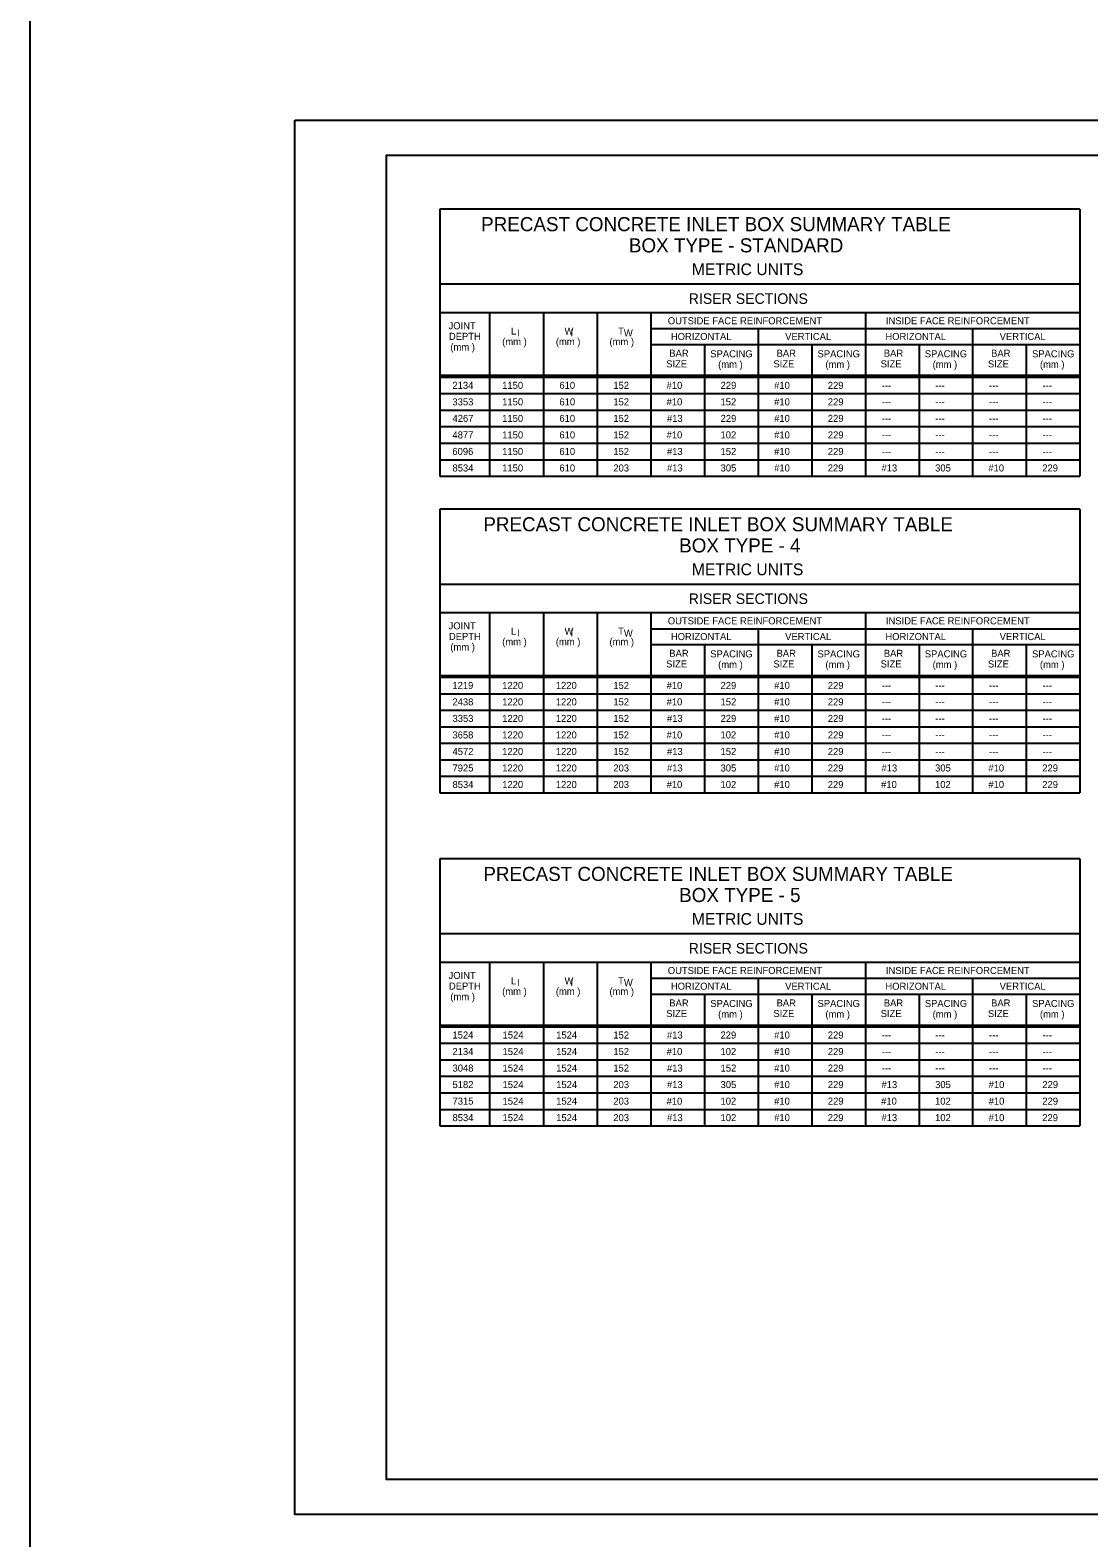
# Model space of a CAD drawing. Extents: x -6420 to 49575, y -4552 to 11624.
# Drawn here: x 34295 to 35776, y -102 to 2006 of the extents above; entities that cross this region are included whole.
import ezdxf

# ---------------------------------------------------------------- set-up
doc = ezdxf.new("R2010")
doc.units = 0
doc.layers.add('1', color=7, linetype='Continuous')
doc.layers.add('4', color=7, linetype='Continuous')

msp = doc.modelspace()

# ---------------------------------------------------------------- linework, layer by layer
at = {"layer": '1'}
for p, q in [((34868.5, 1755.6), (34868.5, 1382.3)), ((35763.5, 1755.6), (34868.5, 1755.6)), ((35763.5, 1755.6), (35763.5, 1382.3)), ((35763.5, 1650.6), (34868.5, 1650.6)), ((35763.5, 1610.6), (34868.5, 1610.6)), ((34938.5, 1382.3), (34938.5, 1610.6)), ((35013.5, 1610.6), (35013.5, 1382.3)), ((35088.5, 1610.6), (35088.5, 1382.3)), ((35163.5, 1610.6), (35163.5, 1382.3)), ((35463.5, 1610.6), (35463.5, 1382.3)), ((35163.5, 1588.6), (35463.5, 1588.6)), ((35313.5, 1588.6), (35313.5, 1382.3)), ((35463.5, 1588.6), (35763.5, 1588.6)), ((35613.5, 1588.6), (35613.5, 1382.3)), ((35163.5, 1566.6), (35463.5, 1566.6)), ((35238.5, 1566.6), (35238.5, 1382.3)), ((35388.5, 1566.6), (35388.5, 1382.3)), ((35463.5, 1566.6), (35763.5, 1566.6)), ((35538.5, 1566.6), (35538.5, 1382.3)), ((35688.5, 1566.6), (35688.5, 1382.3)), ((34868.5, 1523.4), (35763.5, 1523.4)), ((34868.5, 1520.9), (35763.5, 1520.9)), ((34868.5, 1497.8), (35763.5, 1497.8)), ((34868.5, 1474.7), (35763.5, 1474.7)), ((34868.5, 1451.6), (35763.5, 1451.6)), ((34868.5, 1428.5), (35763.5, 1428.5)), ((34868.5, 1405.4), (35763.5, 1405.4)), ((34868.5, 1382.3), (35763.5, 1382.3)), ((34868.5, 1336.1), (34868.5, 939.7)), ((35763.5, 1336.1), (34868.5, 1336.1)), ((35763.5, 1336.1), (35763.5, 939.7)), ((35763.5, 1231.1), (34868.5, 1231.1)), ((35763.5, 1191.1), (34868.5, 1191.1)), ((34938.5, 939.7), (34938.5, 1191.1)), ((35013.5, 1191.1), (35013.5, 939.7)), ((35088.5, 1191.1), (35088.5, 939.7)), ((35163.5, 1191.1), (35163.5, 939.7)), ((35463.5, 1191.1), (35463.5, 939.7)), ((35163.5, 1169.1), (35463.5, 1169.1)), ((35313.5, 1169.1), (35313.5, 939.7)), ((35463.5, 1169.1), (35763.5, 1169.1)), ((35613.5, 1169.1), (35613.5, 939.7)), ((35163.5, 1147.1), (35463.5, 1147.1)), ((35238.5, 1147.1), (35238.5, 939.7)), ((35388.5, 1147.1), (35388.5, 939.7)), ((35463.5, 1147.1), (35763.5, 1147.1)), ((35538.5, 1147.1), (35538.5, 939.7)), ((35688.5, 1147.1), (35688.5, 939.7)), ((34868.5, 1103.9), (35763.5, 1103.9)), ((34868.5, 1101.4), (35763.5, 1101.4)), ((34868.5, 1078.3), (35763.5, 1078.3)), ((34868.5, 1055.2), (35763.5, 1055.2)), ((34868.5, 1032.1), (35763.5, 1032.1)), ((34868.5, 1009), (35763.5, 1009)), ((34868.5, 985.9), (35763.5, 985.9)), ((34868.5, 962.8), (35763.5, 962.8)), ((34868.5, 939.7), (35763.5, 939.7)), ((34868.5, 847.3), (34868.5, 474.1)), ((35763.5, 847.3), (34868.5, 847.3)), ((35763.5, 847.3), (35763.5, 474.1)), ((35763.5, 742.4), (34868.5, 742.4)), ((35763.5, 702.4), (34868.5, 702.4)), ((34938.5, 474.1), (34938.5, 702.4)), ((35013.5, 702.4), (35013.5, 474.1)), ((35088.5, 702.4), (35088.5, 474.1)), ((35163.5, 702.4), (35163.5, 474.1)), ((35463.5, 702.4), (35463.5, 474.1)), ((35163.5, 680.4), (35463.5, 680.4)), ((35313.5, 680.4), (35313.5, 474.1)), ((35463.5, 680.4), (35763.5, 680.4)), ((35613.5, 680.4), (35613.5, 474.1)), ((35163.5, 658.4), (35463.5, 658.4)), ((35238.5, 658.4), (35238.5, 474.1)), ((35388.5, 658.4), (35388.5, 474.1)), ((35463.5, 658.4), (35763.5, 658.4)), ((35538.5, 658.4), (35538.5, 474.1)), ((35688.5, 658.4), (35688.5, 474.1)), ((34868.5, 615.1), (35763.5, 615.1)), ((34868.5, 612.7), (35763.5, 612.7)), ((34868.5, 589.5), (35763.5, 589.5)), ((34868.5, 566.5), (35763.5, 566.5)), ((34868.5, 543.4), (35763.5, 543.4)), ((34868.5, 520.3), (35763.5, 520.3)), ((34868.5, 497.2), (35763.5, 497.2)), ((34868.5, 474.1), (35763.5, 474.1))]:
    msp.add_line(p, q, dxfattribs=at)
msp.add_lwpolyline([(34295.4, 6319.6), (48971.6, 6319.6), (48971.6, -4552.2), (34295.4, -4552.2)], close=True, dxfattribs=at)
msp.add_lwpolyline([(37372.3, -19.8), (37372.3, 1830.6), (34793.5, 1830.6), (34793.5, -19.8), (37372.3, -19.8), (37372.3, 66.7), (36716.1, 66.7), (36716.1, 278.9), (37372.3, 278.9), (37372.3, 373.9), (36716.1, 373.9), (36716.1, -19.8), (36974.7, -19.8), (36974.7, 66.7), (36974.7, -19.8), (37227.3, -19.8), (37227.3, 66.7), (37227.3, 26.3), (37372.3, 26.3)], dxfattribs=at)
at = {"layer": '4'}
msp.add_lwpolyline([(34665.6, 1879.8), (37424.8, 1879.8), (37424.8, -69), (34665.6, -69)], close=True, dxfattribs=at)

# ---------------------------------------------------------------- texts
at = {"layer": '1'}
for s, height, p in [('PRECAST CONCRETE INLET BOX SUMMARY TABLE', 19.685, (34926.1, 1724.8)), ('BOX TYPE - STANDARD', 19.685, (35132.8, 1695.2)), ('METRIC UNITS', 16.404, (35220.8, 1663.4)), ('RISER SECTIONS', 14.764, (35216.4, 1623.2)), ('OUTSIDE FACE REINFORCEMENT', 9.843, (35187.2, 1594.7)), ('INSIDE FACE REINFORCEMENT', 9.843, (35492.2, 1594.7)), ('JOINT', 9.84, (34880.6, 1587.7)), ('DEPTH', 9.84, (34881.1, 1572.9)), ('L ', 9.84, (34967.8, 1580.3)), ('I', 9.84, (34976.8, 1577.7)), ('W ', 9.84, (35042.8, 1580.3)), ('I', 9.84, (35051.2, 1577.8)), ('T ', 9.84, (35117.8, 1580.3)), ('W', 9.84, (35125.8, 1577.6)), ('HORIZONTAL', 9.84, (35191.5, 1572.7)), ('VERTICAL', 9.84, (35351.3, 1572.7)), ('HORIZONTAL', 9.84, (35491.5, 1572.7)), ('VERTICAL', 9.84, (35651.3, 1572.7)), ('(mm )', 9.84, (34883.1, 1558)), ('(mm )', 9.84, (34955.6, 1565.5)), ('(mm )', 9.84, (35030.6, 1565.5)), ('(mm )', 9.84, (35105.6, 1565.5)), ('SIZE', 9.84, (35184.9, 1534.4)), ('BAR', 9.84, (35189.3, 1549.3)), ('SPACING', 9.84, (35246.6, 1548.5)), ('(mm )', 9.84, (35257.6, 1533.7)), ('SIZE', 9.84, (35334.9, 1534.4)), ('BAR', 9.84, (35339.3, 1549.3)), ('SPACING', 9.84, (35396.6, 1548.5)), ('(mm )', 9.84, (35407.6, 1533.7)), ('SIZE', 9.84, (35484.9, 1534.4)), ('BAR', 9.84, (35489.3, 1549.3)), ('SPACING', 9.84, (35546.6, 1548.5)), ('(mm )', 9.84, (35557.6, 1533.7)), ('SIZE', 9.84, (35634.9, 1534.4)), ('BAR', 9.84, (35639.3, 1549.3)), ('SPACING', 9.84, (35696.6, 1548.5)), ('(mm )', 9.84, (35707.6, 1533.7)), ('2134', 9.84, (34886, 1504.4)), ('1150', 9.84, (34955.6, 1504.4)), ('610', 9.84, (35035.6, 1504.4)), ('152', 9.84, (35111, 1504.4)), ('#10', 9.84, (35185.5, 1504.4)), ('229', 9.84, (35261, 1504.4)), ('#10', 9.84, (35335.9, 1504.4)), ('229', 9.84, (35411, 1504.4)), ('---', 9.84, (35486.4, 1504.4)), ('---', 9.84, (35561.4, 1504.4)), ('---', 9.84, (35636.4, 1504.4)), ('---', 9.84, (35711.4, 1504.4)), ('3353', 9.84, (34886, 1481.3)), ('1150', 9.84, (34955.6, 1481.3)), ('610', 9.84, (35035.6, 1481.3)), ('152', 9.84, (35111, 1481.3)), ('#10', 9.84, (35185.5, 1481.3)), ('152', 9.84, (35260.9, 1481.3)), ('#10', 9.84, (35335.9, 1481.3)), ('229', 9.84, (35411, 1481.3)), ('---', 9.84, (35486.4, 1481.3)), ('---', 9.84, (35561.4, 1481.3)), ('---', 9.84, (35636.4, 1481.3)), ('---', 9.84, (35711.4, 1481.3)), ('4267', 9.84, (34886.1, 1458.2)), ('1150', 9.84, (34955.6, 1458.2)), ('610', 9.84, (35035.6, 1458.2)), ('152', 9.84, (35111, 1458.2)), ('#13', 9.84, (35186, 1458.2)), ('229', 9.84, (35261, 1458.2)), ('#10', 9.84, (35335.9, 1458.2)), ('229', 9.84, (35411, 1458.2)), ('---', 9.84, (35486.4, 1458.2)), ('---', 9.84, (35561.4, 1458.2)), ('---', 9.84, (35636.4, 1458.2)), ('---', 9.84, (35711.4, 1458.2)), ('4877', 9.84, (34886, 1435.1)), ('1150', 9.84, (34955.6, 1435.1)), ('610', 9.84, (35035.6, 1435.1)), ('152', 9.84, (35111, 1435.1)), ('#10', 9.84, (35185.5, 1435.1)), ('102', 9.84, (35260.9, 1435.1)), ('#10', 9.84, (35335.9, 1435.1)), ('229', 9.84, (35411, 1435.1)), ('---', 9.84, (35486.4, 1435.1)), ('---', 9.84, (35561.4, 1435.1)), ('---', 9.84, (35636.4, 1435.1)), ('---', 9.84, (35711.4, 1435.1)), ('6096', 9.84, (34885.9, 1412)), ('1150', 9.84, (34955.6, 1412)), ('610', 9.84, (35035.6, 1412)), ('152', 9.84, (35111, 1412)), ('#13', 9.84, (35186, 1412)), ('152', 9.84, (35261, 1412)), ('#10', 9.84, (35335.9, 1412)), ('229', 9.84, (35411, 1412)), ('---', 9.84, (35486.4, 1412)), ('---', 9.84, (35561.4, 1412)), ('---', 9.84, (35636.4, 1412)), ('---', 9.84, (35711.4, 1412)), ('8534', 9.84, (34886.1, 1388.9)), ('1150', 9.84, (34955.6, 1388.9)), ('610', 9.84, (35035.6, 1388.9)), ('203', 9.84, (35111, 1388.9)), ('#13', 9.84, (35186, 1388.9)), ('305', 9.84, (35261, 1388.9)), ('#10', 9.84, (35335.9, 1388.9)), ('229', 9.84, (35410.9, 1388.9)), ('#13', 9.84, (35486, 1388.9)), ('305', 9.84, (35561, 1388.9)), ('#10', 9.84, (35635.5, 1388.9)), ('229', 9.84, (35710.9, 1388.9)), ('PRECAST CONCRETE INLET BOX SUMMARY TABLE', 19.685, (34929.2, 1305.3)), ('BOX TYPE - 4', 19.685, (35203.1, 1275.7)), ('METRIC UNITS', 16.404, (35220.8, 1243.9)), ('RISER SECTIONS', 14.764, (35216.4, 1203.7)), ('OUTSIDE FACE REINFORCEMENT', 9.843, (35187.2, 1175.2)), ('INSIDE FACE REINFORCEMENT', 9.843, (35492.2, 1175.2)), ('JOINT', 9.84, (34880.6, 1168.2)), ('DEPTH', 9.84, (34881.1, 1153.4)), ('L ', 9.84, (34967.8, 1160.8)), ('I', 9.84, (34976.8, 1158.3)), ('W ', 9.84, (35042.8, 1160.8)), ('I', 9.84, (35051.2, 1158.3)), ('T ', 9.84, (35117.8, 1160.8)), ('W', 9.84, (35125.8, 1158.1)), ('HORIZONTAL', 9.84, (35191.5, 1153.2)), ('VERTICAL', 9.84, (35351.3, 1153.2)), ('HORIZONTAL', 9.84, (35491.5, 1153.2)), ('VERTICAL', 9.84, (35651.3, 1153.2)), ('(mm )', 9.84, (34883.1, 1138.6)), ('(mm )', 9.84, (34955.6, 1146)), ('(mm )', 9.84, (35030.6, 1146)), ('(mm )', 9.84, (35105.6, 1146)), ('BAR', 9.84, (35189.3, 1129.8)), ('SPACING', 9.84, (35246.6, 1129)), ('BAR', 9.84, (35339.3, 1129.8)), ('SPACING', 9.84, (35396.6, 1129)), ('BAR', 9.84, (35489.3, 1129.8)), ('SPACING', 9.84, (35546.6, 1129)), ('BAR', 9.84, (35639.3, 1129.8)), ('SPACING', 9.84, (35696.6, 1129)), ('SIZE', 9.84, (35184.9, 1114.9)), ('(mm )', 9.84, (35257.6, 1114.2)), ('SIZE', 9.84, (35334.9, 1114.9)), ('(mm )', 9.84, (35407.6, 1114.2)), ('SIZE', 9.84, (35484.9, 1114.9)), ('(mm )', 9.84, (35557.6, 1114.2)), ('SIZE', 9.84, (35634.9, 1114.9)), ('(mm )', 9.84, (35707.6, 1114.2)), ('1219', 9.84, (34885.9, 1084.9)), ('1220', 9.84, (34955.6, 1084.9)), ('1220', 9.84, (35030.6, 1084.9)), ('152', 9.84, (35111, 1084.9)), ('#10', 9.84, (35185.5, 1084.9)), ('229', 9.84, (35261, 1084.9)), ('#10', 9.84, (35335.9, 1085)), ('229', 9.84, (35411, 1084.9)), ('---', 9.84, (35486.4, 1084.9)), ('---', 9.84, (35561.4, 1084.9)), ('---', 9.84, (35636.4, 1084.9)), ('---', 9.84, (35711.4, 1084.9)), ('2438', 9.84, (34886, 1061.9)), ('1220', 9.84, (34955.6, 1061.9)), ('1220', 9.84, (35030.6, 1061.9)), ('152', 9.84, (35111, 1061.9)), ('#10', 9.84, (35185.5, 1061.9)), ('152', 9.84, (35261, 1061.9)), ('#10', 9.84, (35335.9, 1061.9)), ('229', 9.84, (35411, 1061.9)), ('---', 9.84, (35486.4, 1061.9)), ('---', 9.84, (35561.4, 1061.9)), ('---', 9.84, (35636.4, 1061.9)), ('---', 9.84, (35711.4, 1061.9)), ('3353', 9.84, (34886.1, 1038.8)), ('1220', 9.84, (34955.6, 1038.8)), ('1220', 9.84, (35030.6, 1038.8)), ('152', 9.84, (35111, 1038.8)), ('#13', 9.84, (35186, 1038.8)), ('229', 9.84, (35261, 1038.8)), ('#10', 9.84, (35335.9, 1038.8)), ('229', 9.84, (35411, 1038.8)), ('---', 9.84, (35486.4, 1038.8)), ('---', 9.84, (35561.4, 1038.8)), ('---', 9.84, (35636.4, 1038.8)), ('---', 9.84, (35711.4, 1038.8)), ('3658', 9.84, (34886, 1015.7)), ('1220', 9.84, (34955.6, 1015.7)), ('1220', 9.84, (35030.6, 1015.7)), ('152', 9.84, (35111, 1015.7)), ('#10', 9.84, (35185.5, 1015.7)), ('102', 9.84, (35260.9, 1015.7)), ('#10', 9.84, (35335.9, 1015.7)), ('229', 9.84, (35411, 1015.7)), ('---', 9.84, (35486.4, 1015.7)), ('---', 9.84, (35561.4, 1015.7)), ('---', 9.84, (35636.4, 1015.7)), ('---', 9.84, (35711.4, 1015.7)), ('4572', 9.84, (34886.1, 992.6)), ('1220', 9.84, (34955.6, 992.6)), ('1220', 9.84, (35030.6, 992.6)), ('152', 9.84, (35111, 992.6)), ('#13', 9.84, (35186, 992.6)), ('152', 9.84, (35261, 992.6)), ('#10', 9.84, (35335.9, 992.6)), ('229', 9.84, (35411, 992.6)), ('---', 9.84, (35486.4, 992.6)), ('---', 9.84, (35561.4, 992.6)), ('---', 9.84, (35636.4, 992.6)), ('---', 9.84, (35711.4, 992.6)), ('7925', 9.84, (34886.1, 969.5)), ('1220', 9.84, (34955.6, 969.5)), ('1220', 9.84, (35030.6, 969.5)), ('203', 9.84, (35111, 969.5)), ('#13', 9.84, (35186, 969.5)), ('305', 9.84, (35261, 969.5)), ('#10', 9.84, (35335.9, 969.5)), ('229', 9.84, (35410.9, 969.5)), ('#13', 9.84, (35486, 969.5)), ('305', 9.84, (35561, 969.5)), ('#10', 9.84, (35635.5, 969.5)), ('229', 9.84, (35710.9, 969.5)), ('8534', 9.84, (34886.1, 946.4)), ('1220', 9.84, (34955.6, 946.4)), ('1220', 9.84, (35030.6, 946.4)), ('203', 9.84, (35111, 946.4)), ('#10', 9.84, (35185.5, 946.4)), ('102', 9.84, (35260.9, 946.4)), ('#10', 9.84, (35335.9, 946.4)), ('229', 9.84, (35410.9, 946.4)), ('#10', 9.84, (35485.5, 946.4)), ('102', 9.84, (35560.9, 946.4)), ('#10', 9.84, (35635.5, 946.4)), ('229', 9.84, (35710.9, 946.4)), ('PRECAST CONCRETE INLET BOX SUMMARY TABLE', 19.685, (34929.2, 816.5)), ('BOX TYPE - 5', 19.685, (35203.1, 787)), ('METRIC UNITS', 16.404, (35220.8, 755.2)), ('RISER SECTIONS', 14.764, (35216.4, 715)), ('OUTSIDE FACE REINFORCEMENT', 9.843, (35187.2, 686.4)), ('INSIDE FACE REINFORCEMENT', 9.843, (35492.2, 686.4)), ('JOINT', 9.84, (34880.6, 679.5)), ('DEPTH', 9.84, (34881.1, 664.6)), ('L ', 9.84, (34967.8, 672)), ('I', 9.84, (34976.8, 669.5)), ('W ', 9.84, (35042.8, 672)), ('I', 9.84, (35051.2, 669.5)), ('T ', 9.84, (35117.8, 672)), ('W', 9.84, (35125.8, 669.4)), ('(mm )', 9.84, (34883.1, 649.8)), ('(mm )', 9.84, (34955.6, 657.2)), ('(mm )', 9.84, (35030.6, 657.2)), ('(mm )', 9.84, (35105.6, 657.2)), ('HORIZONTAL', 9.84, (35191.5, 664.4)), ('VERTICAL', 9.84, (35351.3, 664.4)), ('HORIZONTAL', 9.84, (35491.5, 664.4)), ('VERTICAL', 9.84, (35651.3, 664.4)), ('SIZE', 9.84, (35184.9, 626.2)), ('BAR', 9.84, (35189.3, 641)), ('SPACING', 9.84, (35246.6, 640.3)), ('(mm )', 9.84, (35257.6, 625.4)), ('SIZE', 9.84, (35334.9, 626.2)), ('BAR', 9.84, (35339.3, 641)), ('SPACING', 9.84, (35396.6, 640.3)), ('(mm )', 9.84, (35407.6, 625.4)), ('SIZE', 9.84, (35484.9, 626.2)), ('BAR', 9.84, (35489.3, 641)), ('SPACING', 9.84, (35546.6, 640.3)), ('(mm )', 9.84, (35557.6, 625.4)), ('SIZE', 9.84, (35634.9, 626.2)), ('BAR', 9.84, (35639.3, 641)), ('SPACING', 9.84, (35696.6, 640.3)), ('(mm )', 9.84, (35707.6, 625.4)), ('1524', 9.84, (34886, 596.2)), ('1524', 9.84, (34956.1, 596.2)), ('1524', 9.84, (35031.1, 596.2)), ('152', 9.84, (35111, 596.2)), ('#13', 9.84, (35186, 596.2)), ('229', 9.84, (35260.9, 596.2)), ('#10', 9.84, (35335.9, 596.2)), ('229', 9.84, (35411, 596.2)), ('---', 9.84, (35486.4, 596.2)), ('---', 9.84, (35561.4, 596.2)), ('---', 9.84, (35636.4, 596.2)), ('---', 9.84, (35711.4, 596.2)), ('2134', 9.84, (34886, 573.1)), ('1524', 9.84, (34956.1, 573.1)), ('1524', 9.84, (35031.1, 573.1)), ('152', 9.84, (35111, 573.1)), ('#10', 9.84, (35185.5, 573.1)), ('102', 9.84, (35260.9, 573.1)), ('#10', 9.84, (35335.9, 573.1)), ('229', 9.84, (35411, 573.1)), ('---', 9.84, (35486.4, 573.1)), ('---', 9.84, (35561.4, 573.1)), ('---', 9.84, (35636.4, 573.1)), ('---', 9.84, (35711.4, 573.1)), ('3048', 9.84, (34886.1, 550)), ('1524', 9.84, (34956.1, 550)), ('1524', 9.84, (35031.1, 550)), ('152', 9.84, (35111, 550)), ('#13', 9.84, (35186, 550)), ('152', 9.84, (35261, 550)), ('#10', 9.84, (35335.9, 550)), ('229', 9.84, (35411, 550)), ('---', 9.84, (35486.4, 550)), ('---', 9.84, (35561.4, 550)), ('---', 9.84, (35636.4, 550)), ('---', 9.84, (35711.4, 550)), ('5182', 9.84, (34886.1, 526.9)), ('1524', 9.84, (34956.1, 526.9)), ('1524', 9.84, (35031.1, 526.9)), ('203', 9.84, (35111, 526.9)), ('#13', 9.84, (35186, 526.9)), ('305', 9.84, (35261, 526.9)), ('#10', 9.84, (35335.9, 526.9)), ('229', 9.84, (35411, 526.9)), ('#13', 9.84, (35486, 526.9)), ('305', 9.84, (35561, 526.9)), ('#10', 9.84, (35635.9, 526.9)), ('229', 9.84, (35711, 526.9)), ('7315', 9.84, (34886.1, 503.8)), ('1524', 9.84, (34956.1, 503.8)), ('1524', 9.84, (35031.1, 503.8)), ('203', 9.84, (35111, 503.8)), ('#10', 9.84, (35185.5, 503.8)), ('102', 9.84, (35260.9, 503.8)), ('#10', 9.84, (35335.9, 503.8)), ('229', 9.84, (35411, 503.8)), ('#10', 9.84, (35485.5, 503.8)), ('102', 9.84, (35560.9, 503.8)), ('#10', 9.84, (35635.9, 503.8)), ('229', 9.84, (35711, 503.8)), ('8534', 9.84, (34886.1, 480.7)), ('1524', 9.84, (34956.1, 480.7)), ('1524', 9.84, (35031.1, 480.7)), ('203', 9.84, (35111, 480.7)), ('#13', 9.84, (35186, 480.7)), ('102', 9.84, (35261, 480.7)), ('#10', 9.84, (35335.9, 480.7)), ('229', 9.84, (35410.9, 480.7)), ('#13', 9.84, (35486, 480.7)), ('102', 9.84, (35561, 480.7)), ('#10', 9.84, (35635.9, 480.7)), ('229', 9.84, (35710.9, 480.7))]:
    msp.add_text(s, height=height, dxfattribs=at).set_placement(p)

doc.saveas('drawing.dxf')
